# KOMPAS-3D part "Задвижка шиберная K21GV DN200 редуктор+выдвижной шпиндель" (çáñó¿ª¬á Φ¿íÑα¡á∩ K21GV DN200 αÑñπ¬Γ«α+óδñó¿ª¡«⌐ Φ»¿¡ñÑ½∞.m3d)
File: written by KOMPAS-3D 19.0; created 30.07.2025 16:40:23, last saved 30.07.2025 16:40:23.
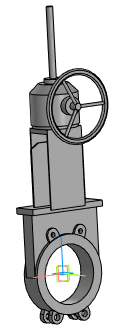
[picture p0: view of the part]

Document properties: Полное имя файла: Задвижка шиберная K21GV DN200 редуктор+выдвижной шпиндель.a3d

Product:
- Part/product: Задвижка шиберная K21GV DN200 редуктор+выдвижной шпиндель
    Масса: 58.4794

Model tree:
1. Операция без истории:1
